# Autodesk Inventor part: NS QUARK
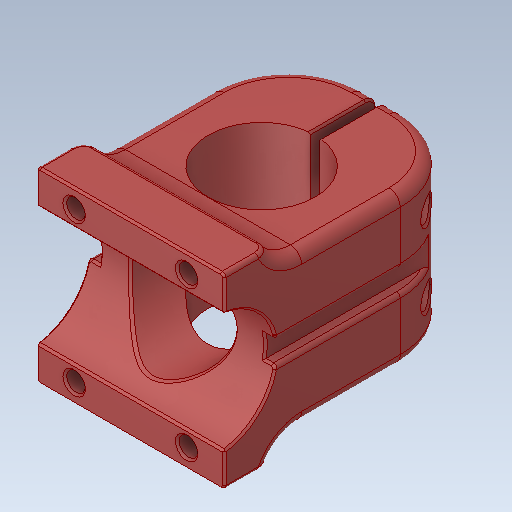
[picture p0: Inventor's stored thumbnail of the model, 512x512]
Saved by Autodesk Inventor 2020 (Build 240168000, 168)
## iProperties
Created: 2015-11
Part Number: NS QUARK
Material: Ogólny
Document SubType Name: Modeling
Designer: Tomasz
Density: 1 g/cm^3
Appearance: Domyślna
Sending System: SolidWorks 2017
Last Author: Tomasz
Last Saved: 2017-09-27
Author: Tomasz
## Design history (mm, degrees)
feature "Imported1"
node "Bryła1"
